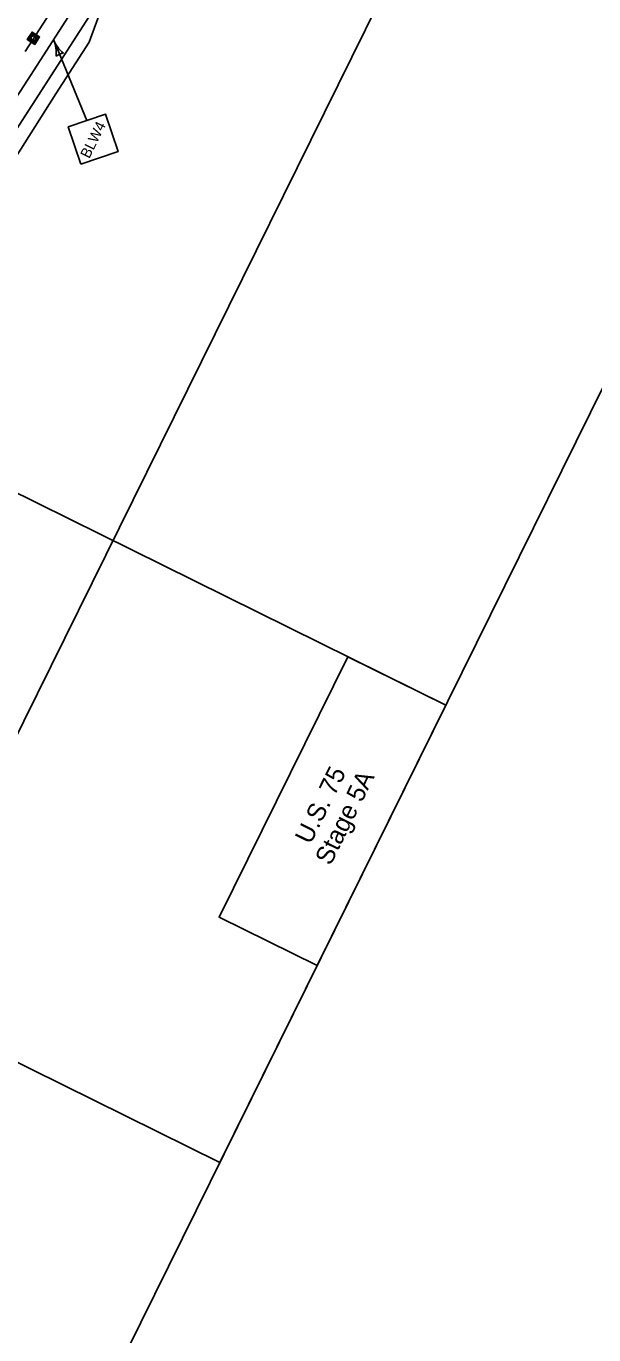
# Model space of a CAD drawing. Extents: x 14104283 to 14129344, y 8637090 to 8673339.
# Drawn here: x 14119404 to 14119794, y 8668379 to 8669277 of the extents above; entities that cross this region are included whole.
import ezdxf

# ---------------------------------------------------------------- set-up
doc = ezdxf.new("R2010")
doc.units = 0
for name, color, linetype in [('dsnCellElements', 7, 'Continuous'), ('dsnNonPlotable', 7, 'Continuous'), ('dsnPaintExistingBrokenLaneLineWhite', 7, 'Continuous'), ('dsnPaintExistingDoubleCenterYellow', 7, 'Continuous'), ('dsnPaintExistingEdgeLineRightWhite', 7, 'Continuous'), ('dsnPaintPlaceBrokenLineWhite', 7, 'Continuous'), ('dsnShadingPaved', 7, 'Continuous'), ('dsnStdLabel', 7, 'Continuous'), ('dsnStgShadingPrevPav', 7, 'Continuous'), ('dsnTextOverlapOdd', 7, 'Continuous')]:
    doc.layers.add(name, color=color, linetype=linetype)

msp = doc.modelspace()

# ---------------------------------------------------------------- linework, layer by layer
at = {"layer": 'dsnCellElements'}
msp.add_circle((14119409.11, 8669268.78), 1.65, dxfattribs=at)
at = {"layer": 'dsnNonPlotable'}
for points in [[(14118631.64, 8668945.1), (14119326.37, 8670350.23), (14120231.75, 8669902.59), (14119537.02, 8668497.46)], [(14118855.74, 8668834.3), (14119550.47, 8670239.43), (14120003.16, 8670015.61), (14119308.43, 8668610.48)], [(14118092.03, 8667853.71), (14118786.76, 8669258.84), (14119692.14, 8668811.2), (14118997.41, 8667406.07)]]:
    msp.add_lwpolyline(points, close=True, dxfattribs=at)
at = {"layer": 'dsnPaintExistingBrokenLaneLineWhite'}
for p, q in [((14119404.97, 8669240.07), (14119490.23, 8669372.15)), ((14119353.59, 8669160.47), (14119404.97, 8669240.07))]:
    msp.add_line(p, q, dxfattribs=at)
at = {"layer": 'dsnPaintExistingDoubleCenterYellow'}
msp.add_line((14119403.44, 8669259.76), (14119494.22, 8669400.39), dxfattribs=at)
at = {"layer": 'dsnPaintExistingEdgeLineRightWhite'}
msp.add_line((14119329.79, 8669101.47), (14119537.52, 8669423.28), dxfattribs=at)
at = {"layer": 'dsnPaintPlaceBrokenLineWhite'}
for p, q in [((14119404.97, 8669240.07), (14119490.23, 8669372.15)), ((14119353.59, 8669160.47), (14119404.97, 8669240.07))]:
    msp.add_line(p, q, dxfattribs=at)
at = {"layer": 'dsnShadingPaved'}
for p, q in [((14119509.78, 8669424.5), (14119403.44, 8669259.76)), ((14119403.44, 8669259.76), (14119477.2, 8669374.02)), ((14119497.33, 8669361.02), (14119415.05, 8669233.56)), ((14119415.05, 8669233.56), (14119367.38, 8669159.7))]:
    msp.add_line(p, q, dxfattribs=at)
at = {"layer": 'dsnStdLabel'}
msp.add_line((14119423.06, 8669267.48), (14119445.85, 8669212.24), dxfattribs=at)
for points in [[(14119410.02, 8669264.55), (14119413.34, 8669269.69), (14119408.2, 8669273.02), (14119404.87, 8669267.87), (14119410.02, 8669264.55)], [(14119410.01, 8669264.55), (14119413.34, 8669269.69), (14119408.2, 8669273.01), (14119404.88, 8669267.87), (14119410.02, 8669264.55)], [(14119410.01, 8669264.55), (14119413.33, 8669269.69), (14119408.2, 8669273.01), (14119404.88, 8669267.87), (14119410.02, 8669264.55)], [(14119410.06, 8669264.69), (14119413.29, 8669269.68), (14119408.21, 8669272.96), (14119404.93, 8669267.88), (14119410.04, 8669264.58)], [(14119410.05, 8669264.73), (14119413.24, 8669269.67), (14119408.22, 8669272.92), (14119404.97, 8669267.89), (14119410.06, 8669264.61)], [(14119410.04, 8669264.78), (14119413.19, 8669269.66), (14119408.23, 8669272.87), (14119405.02, 8669267.9), (14119410.07, 8669264.64)], [(14119410.03, 8669264.82), (14119413.15, 8669269.65), (14119408.24, 8669272.83), (14119405.06, 8669267.91), (14119410.06, 8669264.69)], [(14119410.02, 8669264.87), (14119413.1, 8669269.64), (14119408.25, 8669272.78), (14119405.11, 8669267.92), (14119410.05, 8669264.73)], [(14119410.01, 8669264.91), (14119413.06, 8669269.63), (14119408.26, 8669272.73), (14119405.15, 8669267.93), (14119410.04, 8669264.78)], [(14119410, 8669264.96), (14119413.01, 8669269.62), (14119408.27, 8669272.69), (14119405.2, 8669267.94), (14119410.03, 8669264.82)], [(14119409.99, 8669265), (14119412.97, 8669269.61), (14119408.28, 8669272.64), (14119405.25, 8669267.95), (14119410.02, 8669264.87)], [(14119409.98, 8669265.05), (14119412.92, 8669269.6), (14119408.29, 8669272.6), (14119405.29, 8669267.96), (14119410.01, 8669264.91)], [(14119409.97, 8669265.1), (14119412.88, 8669269.59), (14119408.3, 8669272.55), (14119405.34, 8669267.97), (14119410, 8669264.96)], [(14119409.96, 8669265.14), (14119412.83, 8669269.58), (14119408.31, 8669272.51), (14119405.38, 8669267.98), (14119409.99, 8669265)], [(14119409.95, 8669265.19), (14119412.78, 8669269.57), (14119408.32, 8669272.46), (14119405.43, 8669267.99), (14119409.98, 8669265.05)], [(14119409.94, 8669265.23), (14119412.74, 8669269.56), (14119408.33, 8669272.41), (14119405.47, 8669268), (14119409.97, 8669265.1)], [(14119409.93, 8669265.28), (14119412.69, 8669269.55), (14119408.34, 8669272.37), (14119405.52, 8669268.01), (14119409.96, 8669265.14)], [(14119409.92, 8669265.32), (14119412.65, 8669269.54), (14119408.34, 8669272.32), (14119405.56, 8669268.02), (14119409.95, 8669265.19)], [(14119409.91, 8669265.37), (14119412.6, 8669269.53), (14119408.35, 8669272.28), (14119405.61, 8669268.03), (14119409.94, 8669265.23)], [(14119409.9, 8669265.42), (14119412.56, 8669269.52), (14119408.36, 8669272.23), (14119405.66, 8669268.04), (14119409.93, 8669265.28)], [(14119409.89, 8669265.46), (14119412.51, 8669269.51), (14119408.37, 8669272.19), (14119405.7, 8669268.05), (14119409.92, 8669265.32)], [(14119409.88, 8669265.51), (14119412.46, 8669269.5), (14119408.38, 8669272.14), (14119405.75, 8669268.06), (14119409.91, 8669265.37)], [(14119409.87, 8669265.55), (14119412.42, 8669269.49), (14119408.39, 8669272.1), (14119405.79, 8669268.07), (14119409.9, 8669265.42)], [(14119409.86, 8669265.6), (14119412.37, 8669269.48), (14119408.4, 8669272.05), (14119405.84, 8669268.08), (14119409.89, 8669265.46)], [(14119409.85, 8669265.64), (14119412.33, 8669269.47), (14119408.41, 8669272), (14119405.88, 8669268.09), (14119409.88, 8669265.51)], [(14119409.84, 8669265.69), (14119412.28, 8669269.46), (14119408.42, 8669271.96), (14119405.93, 8669268.1), (14119409.87, 8669265.55)], [(14119409.83, 8669265.73), (14119412.24, 8669269.46), (14119408.43, 8669271.91), (14119405.98, 8669268.11), (14119409.86, 8669265.6)], [(14119409.82, 8669265.78), (14119412.19, 8669269.45), (14119408.44, 8669271.87), (14119406.02, 8669268.12), (14119409.85, 8669265.64)], [(14119409.81, 8669265.83), (14119412.15, 8669269.44), (14119408.45, 8669271.82), (14119406.07, 8669268.13), (14119409.84, 8669265.69)], [(14119409.8, 8669265.87), (14119412.1, 8669269.43), (14119408.46, 8669271.78), (14119406.11, 8669268.14), (14119409.83, 8669265.73)], [(14119409.79, 8669265.92), (14119412.05, 8669269.42), (14119408.47, 8669271.73), (14119406.16, 8669268.15), (14119409.82, 8669265.78)], [(14119409.78, 8669265.96), (14119412.01, 8669269.41), (14119408.48, 8669271.68), (14119406.2, 8669268.16), (14119409.81, 8669265.83)], [(14119409.77, 8669266.01), (14119411.96, 8669269.4), (14119408.49, 8669271.64), (14119406.25, 8669268.17), (14119409.8, 8669265.87)], [(14119409.76, 8669266.05), (14119411.92, 8669269.39), (14119408.5, 8669271.59), (14119406.29, 8669268.18), (14119409.79, 8669265.92)], [(14119409.75, 8669266.1), (14119411.87, 8669269.38), (14119408.51, 8669271.55), (14119406.34, 8669268.19), (14119409.78, 8669265.96)], [(14119409.74, 8669266.15), (14119411.83, 8669269.37), (14119408.52, 8669271.5), (14119406.39, 8669268.2), (14119409.77, 8669266.01)], [(14119409.73, 8669266.19), (14119411.78, 8669269.36), (14119408.53, 8669271.46), (14119406.43, 8669268.21), (14119409.76, 8669266.05)], [(14119409.72, 8669266.24), (14119411.73, 8669269.35), (14119408.54, 8669271.41), (14119406.48, 8669268.22), (14119409.75, 8669266.1)], [(14119409.71, 8669266.28), (14119411.69, 8669269.34), (14119408.55, 8669271.37), (14119406.52, 8669268.23), (14119409.74, 8669266.15)], [(14119409.7, 8669266.33), (14119411.64, 8669269.33), (14119408.56, 8669271.32), (14119406.57, 8669268.24), (14119409.73, 8669266.19)], [(14119409.69, 8669266.37), (14119411.6, 8669269.32), (14119408.57, 8669271.27), (14119406.61, 8669268.25), (14119409.72, 8669266.24)], [(14119409.69, 8669266.42), (14119411.55, 8669269.31), (14119408.58, 8669271.23), (14119406.66, 8669268.26), (14119409.71, 8669266.28)], [(14119409.68, 8669266.47), (14119411.51, 8669269.3), (14119408.59, 8669271.18), (14119406.71, 8669268.27), (14119409.7, 8669266.33)], [(14119409.67, 8669266.51), (14119411.46, 8669269.29), (14119408.6, 8669271.14), (14119406.75, 8669268.28), (14119409.69, 8669266.37)], [(14119409.66, 8669266.56), (14119411.42, 8669269.28), (14119408.61, 8669271.09), (14119406.8, 8669268.29), (14119409.69, 8669266.42)], [(14119409.65, 8669266.6), (14119411.37, 8669269.27), (14119408.62, 8669271.05), (14119406.84, 8669268.3), (14119409.68, 8669266.47)], [(14119407.59, 8669269.39), (14119406.89, 8669268.31), (14119407.98, 8669267.6)], [(14119407.54, 8669269.26), (14119406.93, 8669268.32), (14119407.88, 8669267.71)], [(14119407.52, 8669269.16), (14119406.98, 8669268.33), (14119407.81, 8669267.79)], [(14119407.5, 8669269.07), (14119407.02, 8669268.34), (14119407.76, 8669267.86)], [(14119407.49, 8669268.99), (14119407.07, 8669268.35), (14119407.71, 8669267.93)], [(14119407.48, 8669268.91), (14119407.12, 8669268.35), (14119407.68, 8669267.99)], [(14119407.47, 8669268.85), (14119407.16, 8669268.36), (14119407.64, 8669268.05)], [(14119407.47, 8669268.78), (14119407.21, 8669268.37), (14119407.62, 8669268.11)], [(14119407.47, 8669268.73), (14119407.25, 8669268.38), (14119407.59, 8669268.16)], [(14119407.48, 8669268.67), (14119407.3, 8669268.39), (14119407.57, 8669268.22)], [(14119407.48, 8669268.62), (14119407.34, 8669268.4), (14119407.56, 8669268.27)], [(14119407.49, 8669268.56), (14119407.39, 8669268.41), (14119407.54, 8669268.32)], [(14119407.49, 8669268.51), (14119407.44, 8669268.42), (14119407.53, 8669268.36)], [(14119407.5, 8669268.47), (14119407.48, 8669268.43), (14119407.52, 8669268.41)], [(14119409.72, 8669270.3), (14119408.63, 8669271), (14119407.93, 8669269.91)], [(14119409.58, 8669270.34), (14119408.64, 8669270.95), (14119408.03, 8669270.01)], [(14119409.48, 8669270.37), (14119408.65, 8669270.91), (14119408.11, 8669270.08)], [(14119409.39, 8669270.39), (14119408.66, 8669270.86), (14119408.19, 8669270.13)], [(14119409.31, 8669270.4), (14119408.67, 8669270.82), (14119408.25, 8669270.18)], [(14119409.24, 8669270.41), (14119408.68, 8669270.77), (14119408.32, 8669270.21)], [(14119409.17, 8669270.41), (14119408.69, 8669270.73), (14119408.38, 8669270.24)], [(14119409.11, 8669270.42), (14119408.7, 8669270.68), (14119408.43, 8669270.27)], [(14119409.05, 8669270.41), (14119408.71, 8669270.64), (14119408.49, 8669270.29)], [(14119408.49, 8669267.27), (14119409.67, 8669266.51)], [(14119408.99, 8669270.41), (14119408.72, 8669270.59), (14119408.54, 8669270.31)], [(14119408.94, 8669270.41), (14119408.73, 8669270.54), (14119408.59, 8669270.33)], [(14119408.63, 8669267.22), (14119409.66, 8669266.56)], [(14119408.89, 8669270.4), (14119408.74, 8669270.5), (14119408.64, 8669270.35)], [(14119408.84, 8669270.39), (14119408.75, 8669270.45), (14119408.69, 8669270.36)], [(14119408.79, 8669270.39), (14119408.76, 8669270.41), (14119408.73, 8669270.37)], [(14119408.73, 8669267.19), (14119409.65, 8669266.6)], [(14119408.82, 8669267.17), (14119409.64, 8669266.65)], [(14119408.9, 8669267.16), (14119409.63, 8669266.69)], [(14119408.97, 8669267.15), (14119409.62, 8669266.74)], [(14119409.04, 8669267.15), (14119409.61, 8669266.78)], [(14119409.1, 8669267.15), (14119409.6, 8669266.83)], [(14119409.16, 8669267.15), (14119409.59, 8669266.88)], [(14119409.22, 8669267.15), (14119409.58, 8669266.92)], [(14119409.27, 8669267.16), (14119409.57, 8669266.97)], [(14119409.32, 8669267.16), (14119409.56, 8669267.01)], [(14119409.37, 8669267.17), (14119409.55, 8669267.06)], [(14119409.42, 8669267.18), (14119409.54, 8669267.1)], [(14119409.54, 8669267.1), (14119409.62, 8669267.23)], [(14119409.55, 8669267.06), (14119409.67, 8669267.25)], [(14119409.56, 8669267.01), (14119409.72, 8669267.27)], [(14119409.57, 8669266.97), (14119409.78, 8669267.29)], [(14119409.58, 8669266.92), (14119409.84, 8669267.32)], [(14119409.59, 8669266.88), (14119409.9, 8669267.35)], [(14119409.6, 8669266.83), (14119409.96, 8669267.39)], [(14119409.61, 8669266.78), (14119410.03, 8669267.43)], [(14119409.62, 8669266.74), (14119410.1, 8669267.49)], [(14119409.63, 8669266.69), (14119410.18, 8669267.55)], [(14119409.64, 8669266.65), (14119410.29, 8669267.65)], [(14119410.62, 8669268.17), (14119411.32, 8669269.26), (14119410.24, 8669269.96)], [(14119410.67, 8669268.3), (14119411.28, 8669269.25), (14119410.33, 8669269.86)], [(14119410.7, 8669268.41), (14119411.23, 8669269.24), (14119410.4, 8669269.78)], [(14119410.71, 8669268.5), (14119411.19, 8669269.23), (14119410.46, 8669269.7)], [(14119410.73, 8669268.58), (14119411.14, 8669269.22), (14119410.5, 8669269.63)], [(14119410.73, 8669268.65), (14119411.1, 8669269.21), (14119410.54, 8669269.57)], [(14119410.74, 8669268.72), (14119411.05, 8669269.2), (14119410.57, 8669269.51)], [(14119410.74, 8669268.78), (14119411, 8669269.19), (14119410.59, 8669269.46)], [(14119410.74, 8669268.84), (14119410.96, 8669269.18), (14119410.62, 8669269.4)], [(14119410.74, 8669268.9), (14119410.91, 8669269.17), (14119410.64, 8669269.35)], [(14119410.73, 8669268.95), (14119410.87, 8669269.16), (14119410.66, 8669269.3)], [(14119410.72, 8669269), (14119410.82, 8669269.15), (14119410.67, 8669269.25)], [(14119410.72, 8669269.05), (14119410.78, 8669269.14), (14119410.68, 8669269.2)], [(14119410.71, 8669269.1), (14119410.73, 8669269.13), (14119410.7, 8669269.15)]]:
    msp.add_lwpolyline(points, dxfattribs=at)
msp.add_lwpolyline([(14119441.72, 8669182.34), (14119467.29, 8669190.99), (14119458.64, 8669216.57), (14119433.07, 8669207.91)], close=True, dxfattribs=at)
for centre, radius, start, end in [((14119401.85, 8669258.72), 22.95, 354.35075, 22.42205), ((14119444.28, 8669276.23), 22.95, 202.4219, 230.49317), ((14119430.4, 8669249.69), 8.86, 94.68773, 130.15618)]:
    msp.add_arc(centre, radius, start, end, dxfattribs=at)
at = {"layer": 'dsnStgShadingPrevPav'}
msp.add_lwpolyline([(14119455.82, 8669289.13), (14119447.45, 8669266.1), (14119424.62, 8669230.68), (14119396.25, 8669185.73), (14119365.96, 8669139.11), (14119334.97, 8669091.45), (14119304.91, 8669044.51), (14119267.2, 8668986.39), (14119235.59, 8668937.49), (14119203.77, 8668887.79), (14119172.82, 8668837.38)], dxfattribs=at)
at = {"layer": 'dsnTextOverlapOdd'}
for points in [[(14119692.14, 8668811.2), (14119603.82, 8668632.57), (14119536.59, 8668665.81), (14119624.91, 8668844.44)], [(14119536.59, 8668665.81), (14119624.91, 8668844.44), (14119692.14, 8668811.2), (14119603.82, 8668632.57)]]:
    msp.add_lwpolyline(points, close=True, dxfattribs=at)

# ---------------------------------------------------------------- texts
at = {"layer": 'dsnStdLabel'}
msp.add_text('BLW4', height=7.2, rotation=63.69117, dxfattribs=at).set_placement((14119447.45, 8669185.8))
at = {"layer": 'dsnTextOverlapOdd'}
for s, p in [('U.S. 75', (14119599.33, 8668715.15)), ('Stage 5A', (14119613.08, 8668700.65))]:
    msp.add_text(s, height=12.5, rotation=63.69117, dxfattribs=at).set_placement(p)

doc.saveas('drawing.dxf')
